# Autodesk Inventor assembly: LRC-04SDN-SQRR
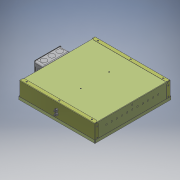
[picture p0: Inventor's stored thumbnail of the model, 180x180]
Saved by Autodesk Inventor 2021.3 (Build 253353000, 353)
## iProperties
load_classification: Lighting
motor: 0 ul
Part Number: LRC-04SDN-SQRR
Document SubType Name: Assembly
Designer: JChurch
description: 0:0:Super Shallow 4" Downlight - COB LED
manufacturer: 0:0:The Kirlin Company
model: 0:0:LRC-04SDN
url: 0:0:
Author: JChurch
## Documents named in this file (6)
- X:\Revit Files\0000-Un-Zipped\COB\LRC-04SDN-SQR\LRC-04SDN-SQRR.iam
- X:\INVENTOR\830\830557-00-00.iam
- X:\INVENTOR\885\885000-00-00.iam
- X:\INVENTOR\750\750206-00-00.iam
- X:\INVENTOR\725\725292-00-00.ipt
- X:\Revit Files\0000-Un-Zipped\COB\LRC-04SDN-SQR\LRC-04SDN-SQRR_Substitute_1.ipt
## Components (5 placed, 5 different names)
1. 830557-00-00:1 [sub-assembly] — Mate:1, Mate:2, Mate:3, Mate:4, Mate:5, Angle:1, Mate:9, Mate:10, Mate:11
2. 885000-00-00:1 [sub-assembly] — Mate:4, Mate:5, Angle:1
3. 750206-00-00:1 [sub-assembly] — Mate:6, Mate:7, Mate:8, Mate:9, Mate:10, Mate:11
4. 725292-00-00:1 — Mate:6, Mate:7, Mate:8
5. LRC-04SDN-SQRR_Substitute_1:1
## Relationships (12: Mate 11, Angle 1)
- Mate:1: 830557-00-00:1
- Mate:2: 830557-00-00:1
- Mate:3: 830557-00-00:1
- Mate:4: 830557-00-00:1 ↔ 885000-00-00:1
- Mate:5: 830557-00-00:1 ↔ 885000-00-00:1
- Angle:1: 830557-00-00:1 ↔ 885000-00-00:1
- Mate:6: 750206-00-00:1 ↔ 725292-00-00:1
- Mate:7: 750206-00-00:1 ↔ 725292-00-00:1
- Mate:8: 750206-00-00:1 ↔ 725292-00-00:1
- Mate:9: 830557-00-00:1 ↔ 750206-00-00:1
- Mate:10: 830557-00-00:1 ↔ 750206-00-00:1
- Mate:11: 830557-00-00:1 ↔ 750206-00-00:1
